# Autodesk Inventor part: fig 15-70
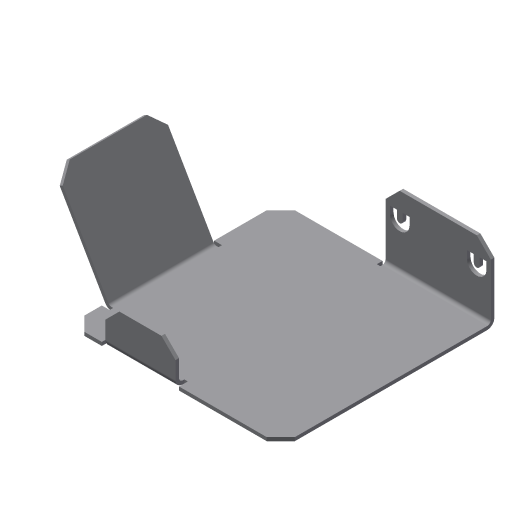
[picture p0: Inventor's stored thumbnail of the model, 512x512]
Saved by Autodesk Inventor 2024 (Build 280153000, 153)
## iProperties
Shininess: 77.0
Angle Display Precision: 2
Document Length Units: 11269
Document Angle Units: 11279
Document Time Units: 11290
Document Mass Units: 11283
Document Length Units Precision: 3
Document Angle Units Precision: 2
Created: 2002-04
Part Number: fig 15-70
Document SubType Name: Sheet Metal
Density: 1 g/cm^3
Sheet Metal Rule: Default
Material: Generic
Appearance: Default
Density: 0.0
Volumn: 0.0
Area: 0.0
PropertySet Name: Model Information
Control State: 0
Master: False
Checked Out: False
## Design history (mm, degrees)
node "Face1"
  sketch "Sketch1"
    geometry: L1 (12.647, 25.882)-(12.647, -14.118); L2 (12.647, -14.118)-(-17.353, -14.118); L3 (-17.353, -14.118)-(-17.353, 15.882); L4 (-17.353, 15.882)-(-2.353, 15.882); L5 (-2.353, 15.882)-(-2.353, 25.882); L6 (-2.353, 25.882)-(12.647, 25.882); 1 further point
    constraints: 12 end point, 4 parallel, 1 perpendicular
    dimensions: "d5" = 30 distance of L2.end L3.end; "d6" = 10 distance of L4.end L5.end; "d7" = 15 distance of L3.end L4.end; "d25" = 15 distance of L5.end L1.start
sketch "Sketch3"
  geometry: L1 (10, -15)-(10, 0)
  constraints: 2 end point
feature "Fold3" sketch "Sketch3" dims "d26" = 0.5 (= BendRadius), "d27" = 90 deg, "d28" = 0.5 (= BendRadius), "d96" = 0.5 (= BendReliefWidth), "d97" = 0.25 (= BendReliefDepth), "d98" = 1 (= MinimumRemnant), "d119" = 0.5 (= Thickness), "SeamGap" = 0.01
node "Flange2"
sketch "Sketch6"
  geometry: L1 (-6.914, 3.413)-(-5.843, 3.413); L2 (-5.843, 0.624)-(-6.914, 0.624); L3 (-6.914, 2.432)-(-5.843, 2.432); L4 (-5.843, 1.605)-(-6.914, 1.605); L5 (-6.914, 0.624)-(-6.914, 1.605); L6 (-6.914, 2.432)-(-6.914, 3.413); L7 (-6.914, 12.568)-(-6.914, 11.587); L8 (-6.914, 14.376)-(-6.914, 13.395); L9 (-6.914, 11.587)-(-5.843, 11.587); L10 (-5.843, 14.376)-(-6.914, 14.376); L11 (-6.914, 12.568)-(-5.843, 12.568); L12 (-5.843, 13.395)-(-6.914, 13.395); A1 r 1.394 centre (-5.843, 2.018) between (-5.843, 0.624) and (-5.843, 3.413); A2 r 0.413 centre (-5.843, 2.018) between (-5.843, 1.605) and (-5.843, 2.432); A3 r 1.394 centre (-5.843, 12.982) between (-5.843, 11.587) and (-5.843, 14.376); A4 r 0.413 centre (-5.843, 12.982) between (-5.843, 12.568) and (-5.843, 13.395)
  constraints: 24 end point, 8 point on circle, 4 centre point, 3 equal length, 1 perpendicular
cut "Cut1" sketch "Sketch6" dims "d49" = 0.5 (= Thickness), "d50" = 0
node "Flange3"
feature "Corner Chamfer3" dims "d107" = 2, "d108" = 6, angle "d109" = 45 deg
feature "Corner Chamfer4" dims "d110" = 2, "d111" = 6, angle "d112" = 45 deg
feature "Corner Chamfer5" dims "d113" = 2, "d114" = 6, angle "d115" = 45 deg
feature "Corner Chamfer6" dims "d116" = 2, "d117" = 6, angle "d118" = 45 deg
body "Solid1"
face "Plate1" dims "d119" = 0.5 (= Thickness)
sketch "Sketch5"
  geometry: L1 (20, 0)-(5, 0); L2 (5, 0)-(5, 15); L3 (5, 15)-(20, 15); L4 (20, 15)-(20, 0)
  constraints: 8 end point
face "Plate6" dims "d35" = 10, "d36" = 5, "d38" = 15, "d39" = 60 deg, "d40" = 0.5 (= BendRadius), "d119" = 0.5 (= Thickness), "MinimumRemnant" = 1 (= 2 x Thickness), "BendReliefWidth" = 0.5 (= Thickness)
bend "Bend5" dims "d38" = 15, "d39" = 60 deg, "d40" = 0.5 (= BendRadius), "d99" = 0.5 (= BendReliefWidth), "d100" = 0.25 (= BendReliefDepth), "d101" = 1 (= MinimumRemnant), "d119" = 0.5 (= Thickness), "SeamGap" = 0.01, "MinimumRemnant" = 1 (= 2 x Thickness), "BendReliefWidth" = 0.5 (= Thickness), "TransitionRadius" = 0.5 (= BendRadius)
sketch "Sketch7"
  geometry: L1 (25, 0)-(15, 0); L2 (15, 0)-(15, 5); L3 (15, 5)-(25, 5); L4 (25, 5)-(25, 0)
  constraints: 8 end point
face "Plate7" dims "d57" = 5, "d58" = 10, "d60" = 5, "d61" = 90 deg, "d62" = 0.5 (= BendRadius), "d119" = 0.5 (= Thickness), "MinimumRemnant" = 1 (= 2 x Thickness), "BendReliefWidth" = 0.5 (= Thickness)
bend "Bend7" dims "d59" = 0.5 (= BendRadius), "d60" = 5, "d61" = 90 deg, "d62" = 0.5 (= BendRadius), "d102" = 0.5 (= BendReliefWidth), "d103" = 0.25 (= BendReliefDepth), "d104" = 1 (= MinimumRemnant), "d119" = 0.5 (= Thickness), "SeamGap" = 0.01, "MinimumRemnant" = 1 (= 2 x Thickness), "BendReliefWidth" = 0.5 (= Thickness)
other parameters: "Thickness" = 0.5, "BendRadius" = 0.5 (= Thickness), "BendReliefDepth" = 0.25 (= 0.5 x Thickness), "CornerReliefSize" = 2 (= 4 x Thickness), "d0" = 0.5 (= BendRadius), "d13" = 0.5 (= BendRadius), "d31" = 0.5 (= BendRadius), "d37" = 0.5 (= BendRadius), "JacobiRadiusSize" = 0.5 (= Thickness), "GapSize" = 0.5 (= Thickness)
